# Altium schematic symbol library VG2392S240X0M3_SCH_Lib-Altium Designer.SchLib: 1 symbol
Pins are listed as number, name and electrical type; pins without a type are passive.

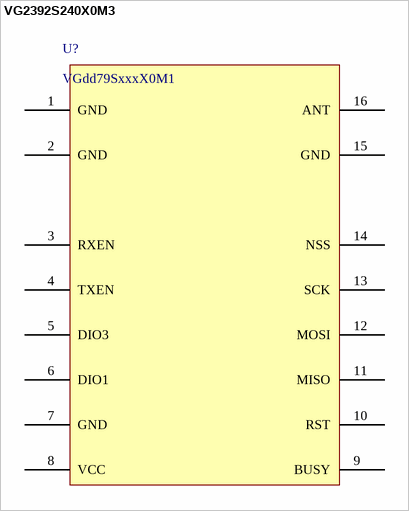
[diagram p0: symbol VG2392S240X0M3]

## VG2392S240X0M3
designator U?, comment VGdd79SxxxX0M1
pins: 1 GND, 2 GND, 3 RXEN, 4 TXEN, 5 DIO3, 6 DIO1, 7 GND, 8 VCC, 9 BUSY, 10 RST, 11 MISO, 12 MOSI, 13 SCK, 14 NSS, 15 GND, 16 ANT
